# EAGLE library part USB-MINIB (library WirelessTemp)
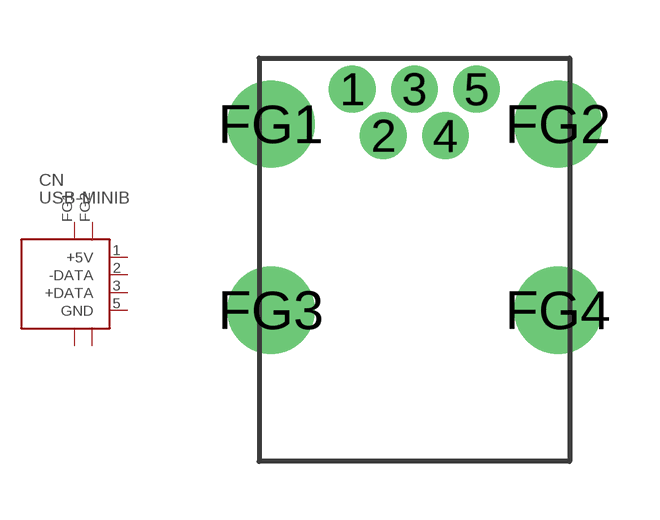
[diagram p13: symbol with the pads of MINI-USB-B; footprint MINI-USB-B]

Designator prefix CN

## USB-MINIB  [MINI-USB-B]
1  +5V  pwr
2  -DATA
3  +DATA
5  GND  pwr
FG1  FG1  pas
FG2  FG2  pas
FG3  FG3  pas
FG4  FG4  pas

## Footprint MINI-USB-B (pad centres in mm)
drill 0.7 pad 1.118 round: 1 -1.6,4.4; 2 -0.8,3.2; 3 0,4.4; 4 0.8,3.2; 5 1.6,4.4
drill 1.5 round: FG1 -3.7,3.5; FG2 3.7,3.5; FG3 -3.7,-1.3; FG4 3.7,-1.3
